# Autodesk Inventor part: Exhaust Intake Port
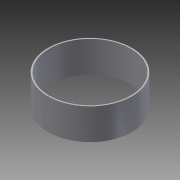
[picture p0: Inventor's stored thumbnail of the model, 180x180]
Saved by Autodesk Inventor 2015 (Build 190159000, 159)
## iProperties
Created: 2006-05
Part Number: Exhaust Intake Port
Document SubType Name: Sheet Metal
Designer: ricara
Density: 2.71 g/cm^3
Material: Aluminum-6061
Mass: 400.863 g
Surface Area: 1014.07 cm^2
Volume: 147.92 cm^3
Sheet Metal Rule: Default
Flat Pattern Width: 7.62 cm
Flat Pattern Length: 63.5732 cm
Flat Pattern Area: 484.427 cm^2
Sheet Metal Width: 76.200 mm
Sheet Metal Length: 635.732 mm
Sheet Metal Area: 48442.750 mm^2
Appearance: Aluminum - Flat
Author: ricara
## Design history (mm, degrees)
derived "MainGeom.ipt"
  sketch "Sketch1"
    geometry: L1 (0, 300)-(-300, 300) reference; L2 (-300, 0)-(-300, 300) reference; L3 (-200, 0)-(-200, -350) reference; L4 (-200, -350)-(200, -350) reference; L5 (200, -350)-(200, 0) reference; C1 r 100 at (0, 0) reference; A1 r 300 centre (0, 0) between (0, 300) and (-300, 0) reference; A2 r 200 centre (0, 0) between (200, 0) and (-200, 0) reference; 1 further point
workplane "Work Plane1"
node "Contour Flange1"
  sketch "Sketch6"
    geometry: L1 (0.5, -99.999)-(0.5, -104.861); L2 (0.5, -104.861)-(-0.5, -104.861); L3 (-0.5, -104.861)-(-0.5, -99.999); L4 (0, -96.582)-(0, 0); C1 r 100 at (0, 0) reference; A1 r 100 centre (0, 0) between (0.5, -99.999) and (-0.5, -99.999)
    constraints: 8 end point, 2 parallel, 2 point on circle, 1 centre point, 1 coincident, 1 concentric, 1 vertical
    dimensions: "d23" = 1 distance of L1.end L2.end
body "Solid1"
face "Plate1" dims "d24" = 3.048 (= BendReliefWidth), "d25" = 1.524 (= BendReliefDepth), "d26" = 6.096 (= MinimumRemnant), "d27" = 3.048 (= BendRadius), "d28" = 76.2, "d29" = 3.048 (= BendRadius), "d30" = 3.048, "d31" = 12.192 (= CornerReliefSize), "d32" = 3.048 (= Thickness), "d33" = 3.048 (= JacobiRadiusSize), "SeamGap" = 0.01, "Thickness" = 3.048
bend "Bend1" dims "d24" = 3.048 (= BendReliefWidth), "d25" = 1.524 (= BendReliefDepth), "d26" = 6.096 (= MinimumRemnant), "d27" = 3.048 (= BendRadius), "d29" = 3.048 (= BendRadius), "d30" = 3.048, "SeamGap" = 0.01, "Thickness" = 3.048
feature "Corner1" dims "d30" = 3.048, "d31" = 12.192 (= CornerReliefSize), "d32" = 3.048 (= Thickness), "d33" = 3.048 (= JacobiRadiusSize)
feature "Definition1" dims "d0" = 3.048 (derived)
other parameters: "t" = 3 [user parameter], "BendRadius" = 3.048 (= Thickness), "BendReliefWidth" = 3.048 (= Thickness), "BendReliefDepth" = 1.524 (= 0.5 x Thickness), "CornerReliefSize" = 12.192 (= 4 x Thickness), "MinimumRemnant" = 6.096 (= 2 x Thickness), "TransitionRadius" = 3.048 (= BendRadius), "JacobiRadiusSize" = 3.048 (= Thickness), "GapSize" = 3.048 (= Thickness), "t" = 3, "BendRadius" = 3.048, "BendReliefDepth" = 1.524, "BendReliefWidth" = 3.048, "CornerReliefSize" = 12.192, "JacobiRadiusSize" = 3.048, "MinimumRemnant" = 6.096, "Thickness" = 3.048, "TransitionRadius" = 3.048, "GapSize" = 3.048
